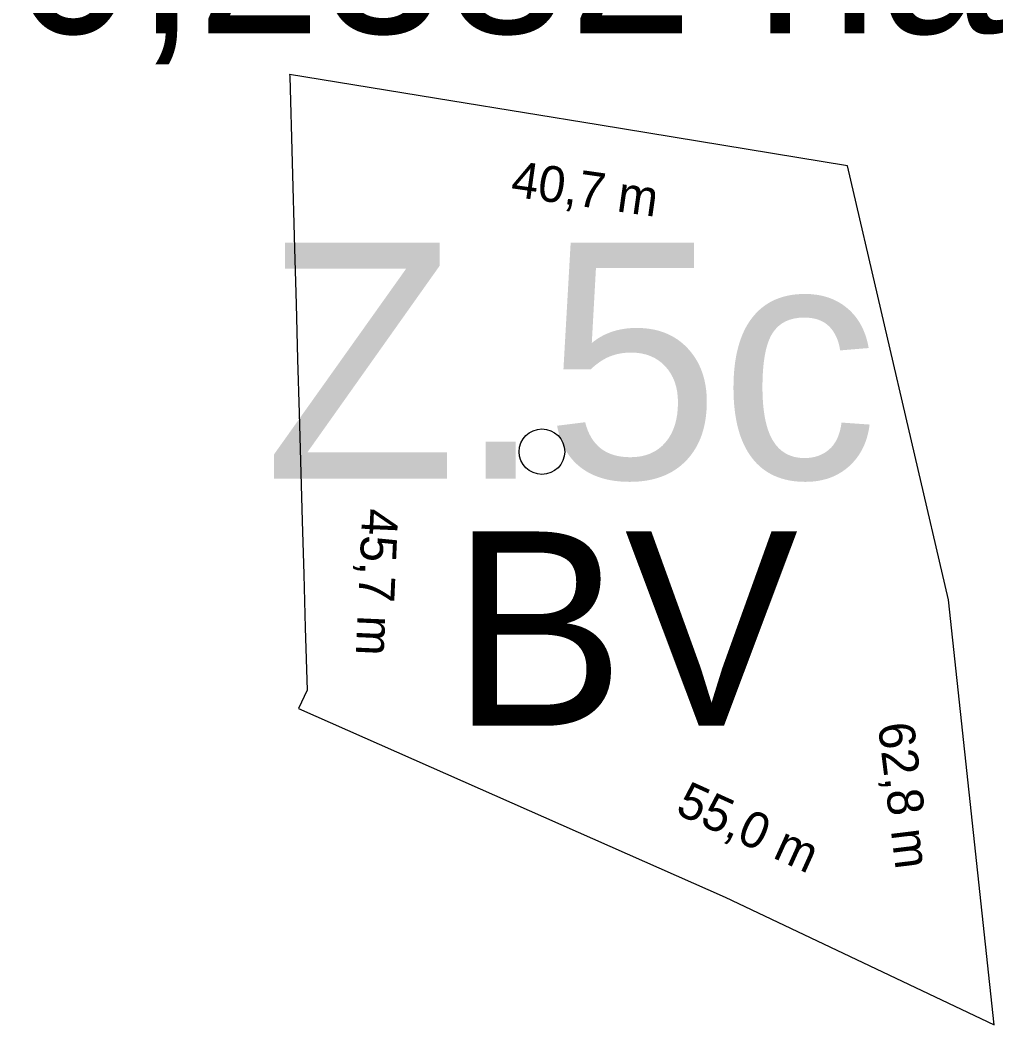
# Model space of a CAD drawing. Extents: x -554894 to -553703, y -1185789 to -1185042.
# Drawn here: x -554402.7 to -554332, y -1185559.1 to -1185486.7 of the extents above; entities that cross this region are included whole.
import ezdxf

# ---------------------------------------------------------------- set-up
doc = ezdxf.new("R2010")
doc.units = 0
for name, color, linetype in [('BILA_TECKA', 7, 'Continuous'), ('ID_navrh', 7, 'Continuous'), ('navrh_BV', 7, 'Continuous'), ('OBRYS_PLOCH', 7, 'Continuous'), ('REGULATIV_navrh', 7, 'Continuous'), ('vymery', 7, 'Continuous'), ('ZASTAVITELNA_PLOCHA', 7, 'Continuous')]:
    doc.layers.add(name, color=color, linetype=linetype)

msp = doc.modelspace()

# ---------------------------------------------------------------- linework, layer by layer
at = {"layer": 'BILA_TECKA'}
msp.add_circle((-554365.155, -1185517.793), 1.639, dxfattribs=at)
at = {"layer": 'navrh_BV'}
for p, q in [((-554371.707, -1185492.513), (-554383.322, -1185490.608)), ((-554383.322, -1185490.608), (-554383.317, -1185490.774)), ((-554371.707, -1185492.513), (-554383.322, -1185490.608)), ((-554383.317, -1185490.774), (-554382.968, -1185503.16)), ((-554361.11, -1185494.25), (-554371.707, -1185492.513)), ((-554361.11, -1185494.25), (-554371.707, -1185492.513)), ((-554343.144, -1185497.196), (-554361.11, -1185494.25)), ((-554343.144, -1185497.196), (-554361.11, -1185494.25)), ((-554382.968, -1185503.16), (-554382.854, -1185507.174)), ((-554382.854, -1185507.174), (-554382.743, -1185511.125)), ((-554382.743, -1185511.125), (-554382.633, -1185515.007)), ((-554382.743, -1185511.125), (-554382.633, -1185515.007)), ((-554382.633, -1185515.007), (-554382.414, -1185522.767)), ((-554382.633, -1185515.007), (-554382.414, -1185522.767)), ((-554382.414, -1185522.767), (-554382.305, -1185526.644)), ((-554382.414, -1185522.767), (-554382.305, -1185526.644)), ((-554382.305, -1185526.644), (-554382.197, -1185530.481)), ((-554382.197, -1185530.481), (-554382.07, -1185534.97)), ((-554382.07, -1185534.97), (-554382.68, -1185536.3)), ((-554382.07, -1185534.97), (-554382.68, -1185536.3))]:
    msp.add_line(p, q, dxfattribs=at)
for points in [[(-554383.322, -1185490.608), (-554383.317, -1185490.774), (-554382.968, -1185503.16), (-554382.854, -1185507.174), (-554382.743, -1185511.125)], [(-554332.599, -1185559.091), (-554335.873, -1185528.469), (-554343.144, -1185497.196)], [(-554332.599, -1185559.091), (-554335.873, -1185528.469), (-554343.144, -1185497.196)], [(-554382.305, -1185526.644), (-554382.197, -1185530.481), (-554382.07, -1185534.97)], [(-554382.68, -1185536.3), (-554351.97, -1185549.89), (-554332.599, -1185559.091)], [(-554382.68, -1185536.3), (-554351.97, -1185549.89), (-554332.599, -1185559.091)]]:
    msp.add_lwpolyline(points, dxfattribs=at)
at = {"layer": 'OBRYS_PLOCH'}
for p, q in [((-554371.707, -1185492.513), (-554383.322, -1185490.608)), ((-554383.322, -1185490.608), (-554383.317, -1185490.774)), ((-554383.317, -1185490.774), (-554382.968, -1185503.16)), ((-554361.11, -1185494.25), (-554371.707, -1185492.513)), ((-554343.144, -1185497.196), (-554361.11, -1185494.25)), ((-554382.968, -1185503.16), (-554382.854, -1185507.174)), ((-554382.854, -1185507.174), (-554382.743, -1185511.125)), ((-554382.743, -1185511.125), (-554382.633, -1185515.007)), ((-554382.633, -1185515.007), (-554382.414, -1185522.767)), ((-554382.414, -1185522.767), (-554382.305, -1185526.644)), ((-554382.305, -1185526.644), (-554382.197, -1185530.481)), ((-554382.197, -1185530.481), (-554382.07, -1185534.97)), ((-554382.07, -1185534.97), (-554382.68, -1185536.3))]:
    msp.add_line(p, q, dxfattribs=at)
for points in [[(-554332.599, -1185559.091), (-554335.873, -1185528.469), (-554343.144, -1185497.196)], [(-554382.68, -1185536.3), (-554351.97, -1185549.89), (-554332.599, -1185559.091)]]:
    msp.add_lwpolyline(points, dxfattribs=at)
at = {"layer": 'ZASTAVITELNA_PLOCHA'}
for p, q in [((-554371.707, -1185492.513), (-554383.322, -1185490.608)), ((-554383.322, -1185490.608), (-554383.317, -1185490.774)), ((-554383.317, -1185490.774), (-554382.968, -1185503.16)), ((-554361.11, -1185494.25), (-554371.707, -1185492.513)), ((-554343.144, -1185497.196), (-554361.11, -1185494.25)), ((-554382.968, -1185503.16), (-554382.854, -1185507.174)), ((-554382.854, -1185507.174), (-554382.743, -1185511.125)), ((-554382.743, -1185511.125), (-554382.633, -1185515.007)), ((-554382.633, -1185515.007), (-554382.414, -1185522.767)), ((-554382.414, -1185522.767), (-554382.305, -1185526.644)), ((-554382.305, -1185526.644), (-554382.197, -1185530.481)), ((-554382.197, -1185530.481), (-554382.07, -1185534.97)), ((-554382.07, -1185534.97), (-554382.68, -1185536.3))]:
    msp.add_line(p, q, dxfattribs=at)
for points in [[(-554332.599, -1185559.091), (-554335.873, -1185528.469), (-554343.144, -1185497.196)], [(-554382.68, -1185536.3), (-554351.97, -1185549.89), (-554332.599, -1185559.091)]]:
    msp.add_lwpolyline(points, dxfattribs=at)

# ---------------------------------------------------------------- texts
at = {"layer": 'ID_navrh'}
msp.add_text('Z.5c', height=17, dxfattribs=at).set_placement((-554385.175, -1185519.725))
at = {"layer": 'REGULATIV_navrh'}
msp.add_text('BV', height=14, dxfattribs=at).set_placement((-554371.683, -1185537.541))
at = {"layer": 'vymery'}
msp.add_text('0,2382 ha', height=12, dxfattribs=at).set_placement((-554403.354, -1185487.651))
for s, rotation, p in [('40,7 m', 351.95053, (-554367.47, -1185499.392)), ('45,7 m', 267.45963, (-554378.084, -1185521.85)), ('62,8 m', 277.01441, (-554340.973, -1185537.439)), ('55,0 m', 335.5966, (-554355.639, -1185543.831))]:
    msp.add_text(s, height=2.592, rotation=rotation, dxfattribs=at).set_placement(p)

doc.saveas('drawing.dxf')
